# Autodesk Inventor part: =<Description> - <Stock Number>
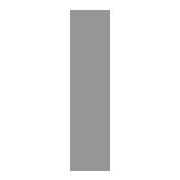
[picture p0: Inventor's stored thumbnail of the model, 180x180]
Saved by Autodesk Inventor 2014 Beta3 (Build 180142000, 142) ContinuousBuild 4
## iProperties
_CCFamilyMember: 149
_CCFamilyDisplayName: ANSI AISC (Rectangular) - Flat Bar Steel
_FrameMemberDoc: Frame Member File
_Version: 15.0.0
_GetPNFromCC: 1
Created: 2010-11
Part Number: =<Description> - <Stock Number>
Material: Steel, Mild
Description: Flat Bar Steel
Document SubType Name: Modeling
Standard: ANSI
Designer: Beta-8540w
Standards Organization: ANSI
Language: en-US
Size Designation: 2 1/4x5/16
Categories: <MemberInstance><Categories><Category DisplayName="Structural Shapes" InternalName="089c4875-fa83-4c05-b084-43b9cc11f5ed" Mnemonic="GRDR"><CategoryParameter Dis
Stock Number: 2 1/4x5/16
Density: 7.86 g/cm^3
Appearance: Steel
IsCustomPart: 1
G_L: 9.325 in
G_W: 0.313 in
G_H: 2.250 in
Author: Beta-8540w
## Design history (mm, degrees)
node "Start plane"
node "End plane"
node "Driven Length"
  sketch "Sketch3"
    geometry: L1 (0, 0)-(10, 0) reference
    constraints: 2 end point, 1 horizontal
  workplane "Work Plane3"
  sketch "Sketch4"
    geometry: L1 (-2, 0)-(12, 0) reference; L2 (-40.005, 236.864)-(40.005, 236.864) reference
    dimensions: "d9" = 236.86413 distance between parallel lines of L1 L2 (derived)
sketch "Sweep Path"
  geometry: L1 through (25.4, 40.279) direction (-1, 0); L2 through (112.121, 127) direction (-1, 0); 9 other entities
  constraints: 10 horizontal
node "Orientation Work Plane"
feature "Body" dims "d10" = 0
body "Solid1"
sketch "Sketch"
  geometry: L1 (3.969, -28.575)-(-3.969, -28.575); L2 (-3.969, -28.575)-(-3.969, 28.575); L3 (-3.969, 28.575)-(3.969, 28.575); L4 (3.969, 28.575)-(3.969, -28.575); L5 (-6, 0)-(8, 0); L6 (0, -30)-(0, 40); L7 (0, 54)-(0, -44); L8 (-9.2, 0)-(13.2, 0)
  constraints: 16 end point, 2 collinear, 2 parallel, 1 horizontal, 1 perpendicular
  dimensions: "d0" = 57.15 distance between parallel lines of L3 L1 (= G_W); "d1" = 7.9375 distance between parallel lines of L4 L2 (= G_H); "d4" = 3.96875 distance between parallel lines of L6 L4 (= 0.5 x d1); "d5" = 28.575 distance between parallel lines of L5 L3 (= 0.5 x d0)
other parameters: "G_W" = 57.15 [user parameter; used in 1 equation term], "G_H" = 7.9375 [user parameter; used in 1 equation term], "G_L" = 236.86413 (= d9) [user parameter], "G_OFFSET_START" = 0 [user parameter; used in 1 equation term], "G_OFFSET_END" = 0 [user parameter; used in 1 equation term], "d6" = 0 (computed from G_OFFSET_START), "d7" = 236.86413 (= G_OFFSET_END + B_L), "B_L" = 236.86413 [user parameter; used in 1 equation term], "d8" = 90 deg
